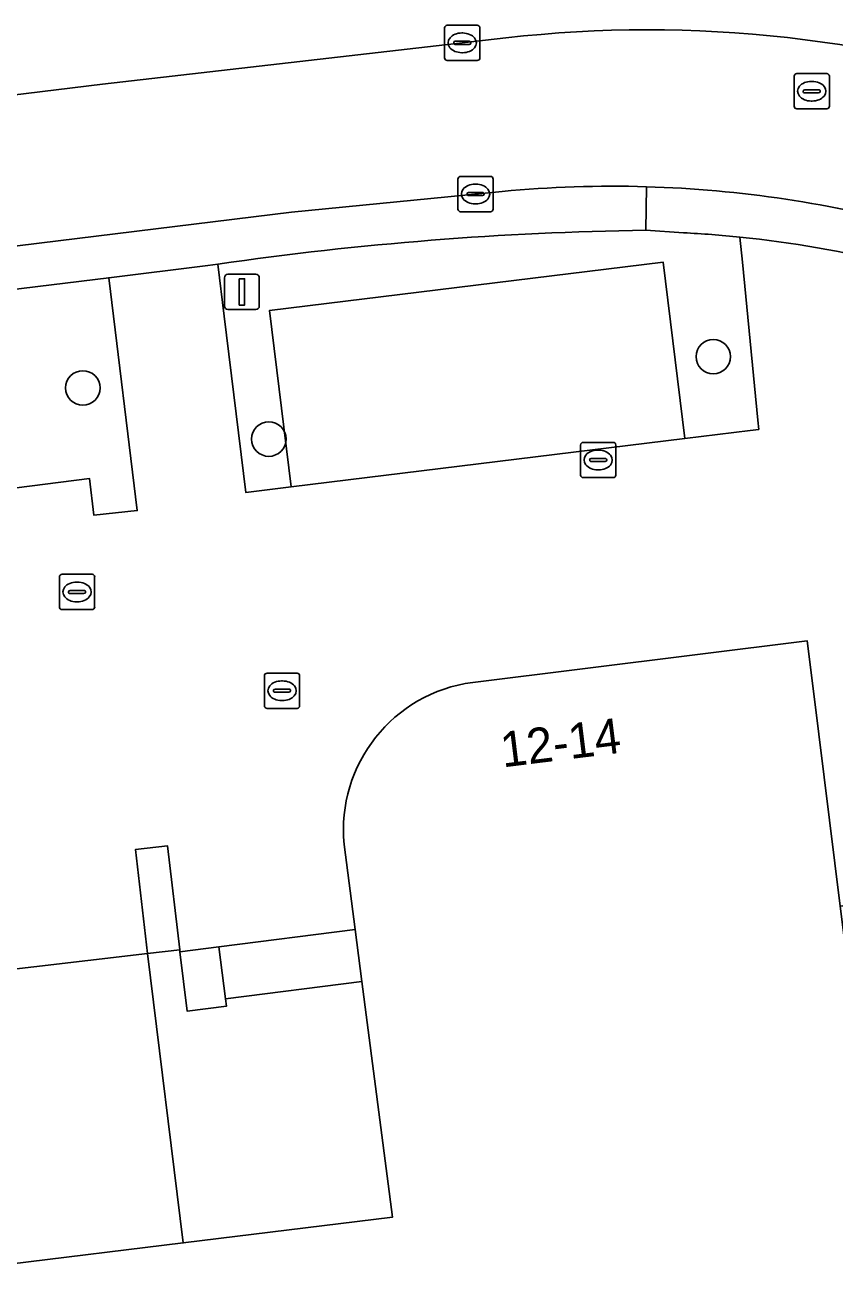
# Model space of a CAD drawing. Extents: x 161477 to 163040, y 383680 to 384871.
# Drawn here: x 161940.05 to 161963.03, y 383988.04 to 384023.82 of the extents above; entities that cross this region are included whole.
import ezdxf

# ---------------------------------------------------------------- set-up
doc = ezdxf.new("R2010")
doc.units = 0
for name, color, linetype in [('IMGEO_Berm_groen', 7, 'Continuous'), ('IMGEO_Boom', 7, 'Continuous'), ('IMGEO_Groenvoorziening', 7, 'Continuous'), ('IMGEO_Kolk', 7, 'Continuous'), ('IMGEO_Lichtmast', 7, 'Continuous'), ('IMGEO_Pand', 7, 'Continuous'), ('IMGEO_Pand_nummerreeks', 7, 'Continuous'), ('IMGEO_Parkeervlak_open', 7, 'Continuous'), ('IMGEO_Rijbaan_lokaal_gesloten', 7, 'Continuous'), ('IMGEO_Rijbaan_lokaal_open', 7, 'Continuous'), ('IMGEO_Rioolput', 7, 'Continuous'), ('IMGEO_Voetpad_gesloten', 7, 'Continuous'), ('IMGEO_Voetpad_op_trap', 7, 'Continuous'), ('IMGEO_Voetpad_open', 7, 'Continuous')]:
    doc.layers.add(name, color=color, linetype=linetype)

msp = doc.modelspace()

# ---------------------------------------------------------------- linework, layer by layer
at = {"layer": 'IMGEO_Berm_groen'}
msp.add_lwpolyline([(161858.533, 384011.921), (161859.469, 384012.052), (161865.698, 384012.787), (161942.24, 384022.146), (161953.69, 384023.463)], dxfattribs=at)
msp.add_arc((161957.72, 383988.002), 35.689, 70.7507, 96.4837, dxfattribs=at)
at = {"layer": 'IMGEO_Boom'}
for centre in [(161959.577, 384014.412), (161941.681, 384013.525), (161946.961, 384012.071)]:
    msp.add_circle(centre, 0.489, dxfattribs=at)
at = {"layer": 'IMGEO_Groenvoorziening'}
for points in [[(161958.733, 384017.931), (161957.662, 384017.999)], [(161945.514, 384017.038), (161945.696, 384015.56), (161946.312, 384010.555), (161947.593, 384010.713), (161946.977, 384015.718), (161958.152, 384017.096), (161958.768, 384012.088), (161960.628, 384012.317), (161960.869, 384012.347), (161960.843, 384012.611), (161960.403, 384017.097), (161960.334, 384017.808)]]:
    msp.add_lwpolyline(points, dxfattribs=at)
for points in [[(161942.419, 384016.653), (161909.941, 384012.689), (161911.231, 384000.416), (161911.306, 383999.708), (161912.799, 383999.865), (161912.741, 384000.409), (161912.251, 384005.077), (161936.764, 384007.928), (161936.813, 384007.584), (161937.489, 384002.813), (161937.564, 384002.823), (161938.193, 384002.912), (161938.893, 384003.011), (161938.827, 384003.48), (161938.22, 384007.825), (161937.988, 384009.484), (161930.999, 384008.59), (161930.899, 384009.549), (161941.867, 384010.958), (161941.996, 384009.912), (161943.227, 384010.041)], [(161944.089, 384000.523), (161943.172, 384000.421), (161943.521, 383997.465), (161944.432, 383997.577)]]:
    msp.add_lwpolyline(points, close=True, dxfattribs=at)
for centre, radius, start, end in [((161958.946, 383924.504), 93.504, 90.7869, 98.25933), ((161956.938, 383984.085), 33.893, 84.2494, 86.9641)]:
    msp.add_arc(centre, radius, start, end, dxfattribs=at)
at = {"layer": 'IMGEO_Kolk'}
for p, q in [((161951.952, 384022.895), (161951.952, 384023.747)), ((161952.027, 384023.821), (161952.879, 384023.821)), ((161952.953, 384023.747), (161952.953, 384022.895)), ((161952.254, 384023.364), (161952.652, 384023.364)), ((161952.44, 384023.601), (161952.465, 384023.601)), ((161952.211, 384023.315), (161952.211, 384023.327)), ((161952.649, 384023.278), (161952.251, 384023.278)), ((161952.463, 384023.041), (161952.438, 384023.041)), ((161952.695, 384023.327), (161952.695, 384023.315)), ((161952.879, 384022.821), (161952.027, 384022.821)), ((161952.329, 384018.602), (161952.329, 384019.454)), ((161952.404, 384019.528), (161953.256, 384019.528)), ((161953.33, 384019.454), (161953.33, 384018.602)), ((161952.631, 384019.071), (161953.029, 384019.071)), ((161952.817, 384019.308), (161952.842, 384019.308)), ((161952.588, 384019.022), (161952.588, 384019.034)), ((161953.026, 384018.985), (161952.628, 384018.985)), ((161952.84, 384018.748), (161952.815, 384018.748)), ((161953.072, 384019.034), (161953.072, 384019.022)), ((161953.256, 384018.528), (161952.404, 384018.528)), ((161955.81, 384011.052), (161955.81, 384011.904)), ((161955.885, 384011.978), (161956.737, 384011.978)), ((161956.811, 384011.904), (161956.811, 384011.052)), ((161956.298, 384011.758), (161956.323, 384011.758)), ((161956.069, 384011.472), (161956.069, 384011.484)), ((161956.507, 384011.435), (161956.109, 384011.435)), ((161956.112, 384011.521), (161956.51, 384011.521)), ((161956.321, 384011.198), (161956.296, 384011.198)), ((161956.553, 384011.484), (161956.553, 384011.472)), ((161956.737, 384010.978), (161955.885, 384010.978)), ((161946.835, 384004.501), (161946.835, 384005.353)), ((161946.91, 384005.427), (161947.762, 384005.427)), ((161947.323, 384005.207), (161947.348, 384005.207)), ((161947.836, 384005.353), (161947.836, 384004.501)), ((161947.094, 384004.921), (161947.094, 384004.933)), ((161947.532, 384004.884), (161947.134, 384004.884)), ((161947.137, 384004.97), (161947.535, 384004.97)), ((161947.578, 384004.933), (161947.578, 384004.921)), ((161947.762, 384004.427), (161946.91, 384004.427)), ((161947.346, 384004.647), (161947.321, 384004.647))]:
    msp.add_line(p, q, dxfattribs=at)
for points in [[(161951.952, 384022.895), (161951.952, 384023.747)], [(161952.027, 384023.821), (161952.879, 384023.821)], [(161952.953, 384023.747), (161952.953, 384022.895)], [(161952.879, 384022.821), (161952.027, 384022.821)], [(161952.329, 384018.602), (161952.329, 384019.454)], [(161952.404, 384019.528), (161953.256, 384019.528)], [(161953.33, 384019.454), (161953.33, 384018.602)], [(161953.256, 384018.528), (161952.404, 384018.528)], [(161955.81, 384011.052), (161955.81, 384011.904)], [(161955.885, 384011.978), (161956.737, 384011.978)], [(161956.811, 384011.904), (161956.811, 384011.052)], [(161956.737, 384010.978), (161955.885, 384010.978)], [(161946.835, 384004.501), (161946.835, 384005.353)], [(161946.91, 384005.427), (161947.762, 384005.427)], [(161947.836, 384005.353), (161947.836, 384004.501)], [(161947.762, 384004.427), (161946.91, 384004.427)]]:
    msp.add_lwpolyline(points, dxfattribs=at)
for centre, radius, start, end in [((161952.029, 384023.745), 0.0765, 91.552, 178.448), ((161952.029, 384023.745), 0.0765, 91.552, 178.448), ((161952.877, 384023.745), 0.0765, 1.552, 88.448), ((161952.877, 384023.745), 0.0765, 1.552, 88.448), ((161952.251, 384023.324), 0.0403, 85.8775, 175.7526), ((161952.656, 384023.326), 0.0386, 1.7309, 96.639), ((161952.248, 384023.314), 0.0366, 178.938, 274.7102), ((161952.652, 384023.321), 0.043, 264.8664, 352.4533), ((161952.029, 384022.897), 0.0765, 181.552, 268.448), ((161952.029, 384022.897), 0.0765, 181.552, 268.448), ((161952.877, 384022.897), 0.0765, 271.552, 358.448), ((161952.877, 384022.897), 0.0765, 271.552, 358.448), ((161952.406, 384019.452), 0.0765, 91.552, 178.448), ((161952.406, 384019.452), 0.0765, 91.552, 178.448), ((161953.254, 384019.452), 0.0765, 1.552, 88.448), ((161953.254, 384019.452), 0.0765, 1.552, 88.448), ((161952.628, 384019.031), 0.0403, 85.8775, 175.7526), ((161953.033, 384019.033), 0.0386, 1.7309, 96.639), ((161952.625, 384019.021), 0.0366, 178.938, 274.7102), ((161953.029, 384019.028), 0.043, 264.8664, 352.4533), ((161952.406, 384018.604), 0.0765, 181.552, 268.448), ((161952.406, 384018.604), 0.0765, 181.552, 268.448), ((161953.254, 384018.604), 0.0765, 271.552, 358.448), ((161953.254, 384018.604), 0.0765, 271.552, 358.448), ((161955.887, 384011.902), 0.0765, 91.552, 178.448), ((161955.887, 384011.902), 0.0765, 91.552, 178.448), ((161956.735, 384011.902), 0.0765, 1.552, 88.448), ((161956.735, 384011.902), 0.0765, 1.552, 88.448), ((161956.109, 384011.481), 0.0403, 85.8775, 175.7526), ((161956.106, 384011.471), 0.0366, 178.938, 274.7102), ((161956.51, 384011.478), 0.043, 264.8664, 352.4533), ((161956.514, 384011.483), 0.0386, 1.7309, 96.639), ((161955.887, 384011.054), 0.0765, 181.552, 268.448), ((161955.887, 384011.054), 0.0765, 181.552, 268.448), ((161956.735, 384011.054), 0.0765, 271.552, 358.448), ((161956.735, 384011.054), 0.0765, 271.552, 358.448), ((161946.912, 384005.351), 0.0765, 91.552, 178.448), ((161946.912, 384005.351), 0.0765, 91.552, 178.448), ((161947.76, 384005.351), 0.0765, 1.552, 88.448), ((161947.76, 384005.351), 0.0765, 1.552, 88.448), ((161947.134, 384004.93), 0.0403, 85.8775, 175.7526), ((161947.131, 384004.92), 0.0366, 178.938, 274.7102), ((161947.535, 384004.927), 0.043, 264.8664, 352.4533), ((161947.539, 384004.932), 0.0386, 1.7309, 96.639), ((161946.912, 384004.503), 0.0765, 181.552, 268.448), ((161946.912, 384004.503), 0.0765, 181.552, 268.448), ((161947.76, 384004.503), 0.0765, 271.552, 358.448), ((161947.76, 384004.503), 0.0765, 271.552, 358.448)]:
    msp.add_arc(centre, radius, start, end, dxfattribs=at)
for centre, major_axis, ratio, start_param, end_param in [((161952.439, 384023.321), (-0.387, 0.002), 0.722429, 4.712389, 7.853982), ((161952.464, 384023.321), (-0.39, 0.002), 0.717154, 1.570796, 4.712389), ((161952.816, 384019.028), (-0.387, 0.002), 0.722429, 4.712389, 7.853982), ((161952.841, 384019.028), (-0.39, 0.002), 0.717154, 1.570796, 4.712389), ((161956.297, 384011.478), (-0.387, 0.002), 0.722429, 4.712389, 7.853982), ((161956.322, 384011.478), (-0.39, 0.002), 0.717154, 1.570796, 4.712389), ((161947.322, 384004.927), (-0.387, 0.002), 0.722429, 4.712389, 7.853982), ((161947.347, 384004.927), (-0.39, 0.002), 0.717154, 1.570796, 4.712389)]:
    msp.add_ellipse(centre, major_axis=major_axis, ratio=ratio, start_param=start_param, end_param=end_param, dxfattribs=at)
at = {"layer": 'IMGEO_Lichtmast'}
for p, q in [((161945.701, 384015.851), (161945.701, 384016.651)), ((161945.701, 384016.651), (161945.701, 384015.851)), ((161945.801, 384016.751), (161946.591, 384016.751)), ((161946.591, 384016.751), (161945.801, 384016.751)), ((161946.691, 384016.651), (161946.691, 384015.851)), ((161946.691, 384015.851), (161946.691, 384016.651)), ((161946.591, 384015.751), (161945.801, 384015.751)), ((161945.801, 384015.751), (161946.591, 384015.751))]:
    msp.add_line(p, q, dxfattribs=at)
msp.add_lwpolyline([(161946.121, 384016.626), (161946.271, 384016.626), (161946.271, 384015.876), (161946.121, 384015.876), (161946.121, 384016.626)], dxfattribs=at)
for centre, start, end in [((161945.801, 384016.651), 90, 180), ((161945.801, 384016.651), 90, 180), ((161946.591, 384016.651), 0, 90), ((161946.591, 384016.651), 360, 90), ((161945.801, 384015.851), 180, 270), ((161945.801, 384015.851), 180, 270), ((161946.591, 384015.851), 270, 0), ((161946.591, 384015.851), 270, 0)]:
    msp.add_arc(centre, 0.1, start, end, dxfattribs=at)
at = {"layer": 'IMGEO_Pand'}
for points in [[(161964.461, 383988.274), (161963.811, 383993.739), (161963.396, 383997.077), (161963.181, 383998.816), (161962.423, 384004.917), (161962.246, 384006.341), (161952.749, 384005.163)], [(161949.098, 384000.565), (161949.412, 383998.153), (161949.604, 383996.676), (161950.476, 383989.986), (161944.534, 383989.254), (161939.601, 383988.646), (161939.204, 383988.597), (161939.001, 383990.24), (161919.858, 383987.878), (161922.541, 383965.891), (161923.153, 383960.88), (161924.788, 383947.478), (161955.119, 383951.24), (161955.133, 383951.147), (161955.356, 383949.45), (161969.073, 383951.131), (161968.408, 383956.619), (161965.92, 383976.575), (161964.461, 383988.274)]]:
    msp.add_lwpolyline(points, dxfattribs=at)
msp.add_arc((161953.297, 384000.979), 4.219, 97.4614, 185.6366, dxfattribs=at)
at = {"layer": 'IMGEO_Parkeervlak_open'}
msp.add_lwpolyline([(161946.977, 384015.718), (161947.593, 384010.713), (161958.768, 384012.088), (161958.152, 384017.096)], close=True, dxfattribs=at)
at = {"layer": 'IMGEO_Rijbaan_lokaal_gesloten'}
for points in [[(161953.69, 384023.463), (161942.24, 384022.146), (161865.698, 384012.787), (161859.469, 384012.052), (161858.533, 384011.921)], [(161857.664, 384007.489), (161861.392, 384007.951), (161861.422, 384007.955), (161865.32, 384008.454), (161899.904, 384012.667), (161908.859, 384013.757), (161947.609, 384018.515), (161953.587, 384019.102)]]:
    msp.add_lwpolyline(points, dxfattribs=at)
for points in [[(161943.521, 383997.465), (161938.584, 383996.887), (161939.601, 383988.646), (161944.534, 383989.254)], [(161949.604, 383996.676), (161945.729, 383996.179), (161945.755, 383995.97), (161944.646, 383995.828), (161944.439, 383997.515), (161944.432, 383997.577), (161943.521, 383997.465), (161944.534, 383989.254), (161950.476, 383989.986)]]:
    msp.add_lwpolyline(points, close=True, dxfattribs=at)
for centre, radius, start, end in [((161957.72, 383988.002), 35.689, 70.7507, 96.4837), ((161956.706, 383986.424), 32.827, 88.2936, 95.453), ((161956.72, 383986.183), 33.067, 74.5816, 88.3289)]:
    msp.add_arc(centre, radius, start, end, dxfattribs=at)
at = {"layer": 'IMGEO_Rijbaan_lokaal_open'}
for points in [[(161960.334, 384017.808), (161960.403, 384017.097), (161960.843, 384012.611), (161960.869, 384012.347), (161960.628, 384012.317), (161958.768, 384012.088), (161947.593, 384010.713), (161946.312, 384010.555), (161945.696, 384015.56), (161945.514, 384017.038), (161945.225, 384016.996), (161942.419, 384016.653), (161943.227, 384010.041), (161941.996, 384009.912), (161941.867, 384010.958), (161930.899, 384009.549)], [(161952.749, 384005.163), (161962.246, 384006.341), (161962.423, 384004.917), (161963.181, 383998.816), (161965.556, 383999.127), (161982.473, 384000.882), (161985.371, 384001.262), (161985.88, 384003.477), (161985.946, 384003.746), (161986.011, 384004.007), (161986.659, 384006.909), (161986.927, 384008.042), (161987.23, 384009.325), (161987.644, 384009.227), (161987.93, 384010.387), (161990.476, 384010.279), (161990.687, 384009.099), (161991.117, 384009.147), (161991.058, 384011.902)], [(161938.584, 383996.887), (161943.521, 383997.465), (161943.172, 384000.421), (161944.089, 384000.523), (161944.432, 383997.577), (161944.439, 383997.515), (161945.539, 383997.656), (161949.412, 383998.153), (161949.098, 384000.565)]]:
    msp.add_lwpolyline(points, dxfattribs=at)
for centre, radius, start, end in [((161957.082, 383986.276), 31.699, 76.0849, 84.1116), ((161953.297, 384000.979), 4.219, 97.4614, 185.6366)]:
    msp.add_arc(centre, radius, start, end, dxfattribs=at)
at = {"layer": 'IMGEO_Rioolput'}
for p, q in [((161961.872, 384021.522), (161961.872, 384022.374)), ((161961.947, 384022.448), (161962.799, 384022.448)), ((161962.873, 384022.374), (161962.873, 384021.522)), ((161962.131, 384021.942), (161962.131, 384021.954)), ((161962.174, 384021.991), (161962.572, 384021.991)), ((161962.36, 384022.228), (161962.385, 384022.228)), ((161962.615, 384021.954), (161962.615, 384021.942)), ((161962.569, 384021.905), (161962.171, 384021.905)), ((161962.383, 384021.668), (161962.358, 384021.668)), ((161962.799, 384021.448), (161961.947, 384021.448)), ((161941.016, 384007.307), (161941.016, 384008.159)), ((161941.091, 384008.233), (161941.943, 384008.233)), ((161941.504, 384008.013), (161941.529, 384008.013)), ((161942.017, 384008.159), (161942.017, 384007.307)), ((161941.275, 384007.727), (161941.275, 384007.739)), ((161941.713, 384007.69), (161941.315, 384007.69)), ((161941.318, 384007.776), (161941.716, 384007.776)), ((161941.759, 384007.739), (161941.759, 384007.727)), ((161941.527, 384007.453), (161941.502, 384007.453)), ((161941.943, 384007.233), (161941.091, 384007.233))]:
    msp.add_line(p, q, dxfattribs=at)
for points in [[(161961.872, 384021.522), (161961.872, 384022.374)], [(161961.947, 384022.448), (161962.799, 384022.448)], [(161962.873, 384022.374), (161962.873, 384021.522)], [(161962.799, 384021.448), (161961.947, 384021.448)], [(161941.016, 384007.307), (161941.016, 384008.159)], [(161941.091, 384008.233), (161941.943, 384008.233)], [(161942.017, 384008.159), (161942.017, 384007.307)], [(161941.943, 384007.233), (161941.091, 384007.233)]]:
    msp.add_lwpolyline(points, dxfattribs=at)
for centre, radius, start, end in [((161961.949, 384022.372), 0.0765, 91.552, 178.448), ((161961.949, 384022.372), 0.0765, 91.552, 178.448), ((161962.797, 384022.372), 0.0765, 1.552, 88.448), ((161962.797, 384022.372), 0.0765, 1.552, 88.448), ((161962.171, 384021.951), 0.0403, 85.8775, 175.7526), ((161962.168, 384021.941), 0.0366, 178.938, 274.7102), ((161962.572, 384021.948), 0.043, 264.8664, 352.4533), ((161962.576, 384021.953), 0.0386, 1.7309, 96.639), ((161961.949, 384021.524), 0.0765, 181.552, 268.448), ((161961.949, 384021.524), 0.0765, 181.552, 268.448), ((161962.797, 384021.524), 0.0765, 271.552, 358.448), ((161962.797, 384021.524), 0.0765, 271.552, 358.448), ((161941.093, 384008.157), 0.0765, 91.552, 178.448), ((161941.093, 384008.157), 0.0765, 91.552, 178.448), ((161941.941, 384008.157), 0.0765, 1.552, 88.448), ((161941.941, 384008.157), 0.0765, 1.552, 88.448), ((161941.315, 384007.736), 0.0403, 85.8775, 175.7526), ((161941.312, 384007.726), 0.0366, 178.938, 274.7102), ((161941.716, 384007.733), 0.043, 264.8664, 352.4533), ((161941.72, 384007.738), 0.0386, 1.7309, 96.639), ((161941.093, 384007.309), 0.0765, 181.552, 268.448), ((161941.093, 384007.309), 0.0765, 181.552, 268.448), ((161941.941, 384007.309), 0.0765, 271.552, 358.448), ((161941.941, 384007.309), 0.0765, 271.552, 358.448)]:
    msp.add_arc(centre, radius, start, end, dxfattribs=at)
for centre, major_axis, ratio, start_param, end_param in [((161962.359, 384021.948), (-0.387, 0.002), 0.722429, 4.712389, 7.853982), ((161962.384, 384021.948), (-0.39, 0.002), 0.717154, 1.570796, 4.712389), ((161941.503, 384007.733), (-0.387, 0.002), 0.722429, 4.712389, 7.853982), ((161941.528, 384007.733), (-0.39, 0.002), 0.717154, 1.570796, 4.712389)]:
    msp.add_ellipse(centre, major_axis=major_axis, ratio=ratio, start_param=start_param, end_param=end_param, dxfattribs=at)
at = {"layer": 'IMGEO_Voetpad_gesloten'}
msp.add_lwpolyline([(161945.539, 383997.656), (161944.439, 383997.515), (161944.646, 383995.828), (161945.755, 383995.97), (161945.729, 383996.179)], close=True, dxfattribs=at)
at = {"layer": 'IMGEO_Voetpad_op_trap'}
msp.add_lwpolyline([(161949.412, 383998.153), (161945.539, 383997.656), (161945.729, 383996.179), (161949.604, 383996.676)], close=True, dxfattribs=at)
at = {"layer": 'IMGEO_Voetpad_open'}
for points in [[(161953.587, 384019.102), (161947.609, 384018.515), (161908.859, 384013.757), (161909.001, 384012.574), (161909.941, 384012.689), (161942.419, 384016.653)], [(161957.662, 384017.999), (161957.684, 384019.236)], [(161957.684, 384019.236), (161957.662, 384017.999), (161958.733, 384017.931)], [(161942.419, 384016.653), (161945.225, 384016.996), (161945.514, 384017.038)]]:
    msp.add_lwpolyline(points, dxfattribs=at)
for centre, radius, start, end in [((161956.706, 383986.424), 32.827, 88.2936, 95.453), ((161956.72, 383986.183), 33.067, 74.5816, 88.3289), ((161958.946, 383924.504), 93.504, 90.7869, 98.25933), ((161956.938, 383984.085), 33.893, 84.2494, 86.9641), ((161957.082, 383986.276), 31.699, 76.0849, 84.1116)]:
    msp.add_arc(centre, radius, start, end, dxfattribs=at)

# ---------------------------------------------------------------- texts
at = {"layer": 'IMGEO_Pand_nummerreeks'}
msp.add_text('12-14', height=1, rotation=7.0703, dxfattribs=at).set_placement((161953.603, 384002.75))

doc.saveas('drawing.dxf')
